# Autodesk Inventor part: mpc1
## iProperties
Shininess: 64.0
Length Units: 11269
Angle Units: 11279
Time Units: 11290
Mass Units: 11283
Length Display Precision: 3
Angle Display Precision: 2
Compacted: True
Part Number: mpc1
Document SubType Name: Modeling
Created: 2004-07
Designer: Peter
Manufacturer: Standard
Standards Organization: Custom
Density: 0.0
Volumn: 0.0
Area: 0.0
PropertySet Name: Model Information
Control State: 0
Master: False
Checked Out: False
Author: Peter
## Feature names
1. Extrusion1
